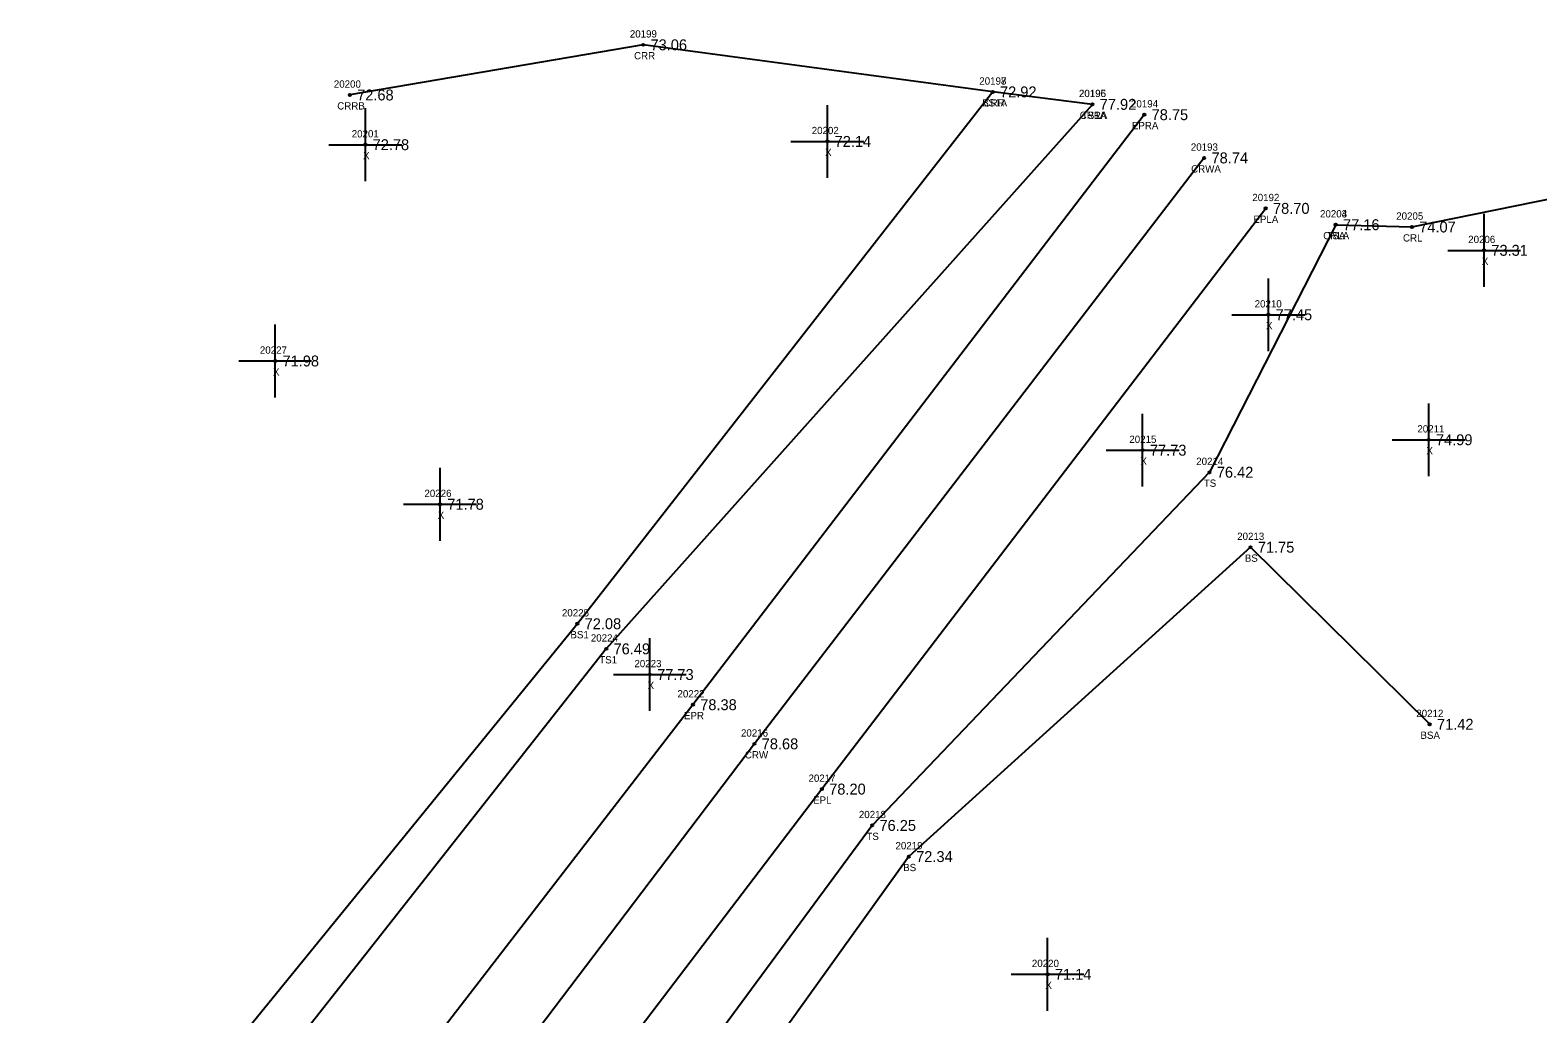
# Model space of a CAD drawing. Extents: x 2505300 to 2506184, y 912965 to 913825.
# Drawn here: x 2505870.9 to 2506078.1, y 913689.6 to 913824.7 of the extents above; entities that cross this region are included whole.
import ezdxf

# ---------------------------------------------------------------- set-up
doc = ezdxf.new("R2010")
doc.units = 0
for name, color, linetype in [('RD_DTM_BkLn1', 7, 'Continuous'), ('RD_DTM_BkLn2', 7, 'Continuous'), ('RD_DTM_BkLn_txCode', 7, 'Continuous'), ('RD_EX_H2O', 7, 'Continuous'), ('RD_EX_H2O_txCode', 7, 'Continuous'), ('RD_EX_Misc', 7, 'Continuous'), ('RD_EX_Misc_txCode', 7, 'Continuous'), ('RD_EX_Road', 7, 'Continuous'), ('RD_EX_Road_txCode', 7, 'Continuous'), ('RD_EX_TX_H2O_ELEV', 7, 'Continuous'), ('RD_EX_TX_Misc_ELEV', 7, 'Continuous'), ('RD_EX_TX_Road_ELEV', 7, 'Continuous'), ('RD_HC_Survey_ELEV', 7, 'Continuous'), ('RD_HC_Survey_txCode', 7, 'Continuous'), ('RD_SMD_Locator', 7, 'Continuous')]:
    doc.layers.add(name, color=color, linetype=linetype)

msp = doc.modelspace()

# ---------------------------------------------------------------- linework, layer by layer
at = {"layer": 'RD_DTM_BkLn1'}
msp.add_lwpolyline([(2506032.26, 913807.16), (2505970.46, 913726.68), (2505911.98, 913649.53), (2505850.51, 913569.34), (2505823.85, 913534.92)], dxfattribs=at)
at = {"layer": 'RD_DTM_BkLn2'}
for points in [[(2506003.2, 913816.23), (2505946.13, 913743.18), (2505885.35, 913668.51), (2505838.59, 913602.48), (2505816.98, 913593.69), (2505806.53, 913576.86), (2505793.9, 913560.45)], [(2506016.9, 913814.52), (2505950.1, 913739.73), (2505890.95, 913664.65), (2505842.78, 913598.78), (2505826.57, 913582.25), (2505819.44, 913586.46), (2505803.76, 913558.88), (2505804.05, 913552.09), (2505810.12, 913545.7)], [(2506050.33, 913797.99), (2506032.99, 913763.99), (2505986.64, 913715.48), (2505928.41, 913636.56), (2505869.01, 913554.3), (2505845.62, 913525.11), (2505838.24, 913524.07)], [(2506063.24, 913729.37), (2506038.62, 913753.69), (2505991.68, 913711.2), (2505934.4, 913631.37), (2505905.82, 913578.23), (2505899.85, 913572.14), (2505876.49, 913544.36), (2505856.4, 913524.92), (2505848.42, 913517.19)]]:
    msp.add_lwpolyline(points, dxfattribs=at)
at = {"layer": 'RD_EX_H2O'}
for points in [[(2506016.9, 913814.52), (2506003.2, 913816.23), (2505955.18, 913822.7), (2505914.87, 913815.81)], [(2506050.33, 913797.99), (2506060.8, 913797.68), (2506089.41, 913803.52), (2506128.64, 913810.3)]]:
    msp.add_lwpolyline(points, dxfattribs=at)
at = {"layer": 'RD_EX_Misc'}
for p, q in [((2505917, 913803.98), (2505917, 913813.98)), ((2505980.48, 913804.43), (2505980.48, 913814.43)), ((2505975.48, 913809.43), (2505985.48, 913809.43)), ((2505912, 913808.98), (2505922, 913808.98)), ((2506070.71, 913789.47), (2506070.71, 913799.47)), ((2506065.71, 913794.47), (2506075.71, 913794.47)), ((2506041.07, 913780.62), (2506041.07, 913790.62)), ((2506036.07, 913785.62), (2506046.07, 913785.62)), ((2505904.62, 913774.27), (2505904.62, 913784.27)), ((2505899.62, 913779.27), (2505909.62, 913779.27)), ((2506023.8, 913762.02), (2506023.8, 913772.02)), ((2506063.1, 913763.45), (2506063.1, 913773.45)), ((2506058.1, 913768.45), (2506068.1, 913768.45)), ((2506018.8, 913767.02), (2506028.8, 913767.02)), ((2505927.26, 913754.59), (2505927.26, 913764.59)), ((2505922.26, 913759.59), (2505932.26, 913759.59)), ((2505956.09, 913731.21), (2505956.09, 913741.21)), ((2505951.09, 913736.21), (2505961.09, 913736.21)), ((2506010.74, 913690.03), (2506010.74, 913700.03)), ((2506005.74, 913695.03), (2506015.74, 913695.03))]:
    msp.add_line(p, q, dxfattribs=at)
at = {"layer": 'RD_EX_Road'}
for points in [[(2506024.03, 913813.1), (2505962.01, 913732.06), (2505903.3, 913655.93), (2505840.88, 913574.4), (2505819.41, 913546.54), (2505814.19, 913542.64)], [(2506040.71, 913800.23), (2505979.73, 913720.47), (2505920.44, 913642.61), (2505859.42, 913562.61), (2505835.44, 913531.43), (2505833.77, 913527.25)]]:
    msp.add_lwpolyline(points, dxfattribs=at)
at = {"layer": 'RD_SMD_Locator'}
for centre in [(2505955.18, 913822.7), (2505914.87, 913815.81), (2506003.2, 913816.23), (2506003.2, 913816.23), (2506016.9, 913814.52), (2506016.9, 913814.52), (2506024.03, 913813.1), (2505980.48, 913809.43), (2505917, 913808.98), (2506032.26, 913807.16), (2506040.71, 913800.23), (2506050.33, 913797.99), (2506050.33, 913797.99), (2506060.8, 913797.68), (2506070.71, 913794.47), (2506041.07, 913785.62), (2505904.62, 913779.27), (2506063.1, 913768.45), (2506023.8, 913767.02), (2506032.99, 913763.99), (2505927.26, 913759.59), (2506038.62, 913753.69), (2505946.13, 913743.18), (2505950.1, 913739.73), (2505956.09, 913736.21), (2505962.01, 913732.06), (2506063.24, 913729.37), (2505970.46, 913726.68), (2505979.73, 913720.47), (2505986.64, 913715.48), (2505991.68, 913711.2), (2506010.74, 913695.03)]:
    msp.add_circle(centre, 0.15, dxfattribs=at)

# ---------------------------------------------------------------- texts
at = {"layer": 'RD_DTM_BkLn_txCode'}
for s, p in [('20198', (2506001.36, 913817.23)), ('20195', (2506015.06, 913815.52)), ('BS1A', (2506001.76, 913814.23)), ('TS1A', (2506015.45, 913812.52)), ('20203', (2506048.17, 913798.99)), ('TSA', (2506049.05, 913795.99)), ('20214', (2506031.16, 913764.99)), ('TS', (2506032.2, 913761.99)), ('20213', (2506036.79, 913754.69)), ('BS', (2506037.84, 913751.69)), ('20225', (2505944.01, 913744.18)), ('BS1', (2505945.18, 913741.18)), ('20224', (2505947.98, 913740.73)), ('TS1', (2505949.14, 913737.73)), ('20212', (2506061.4, 913730.37)), ('BSA', (2506061.97, 913727.37)), ('20218', (2505984.81, 913716.48)), ('TS', (2505985.84, 913713.48)), ('20219', (2505989.84, 913712.2)), ('BS', (2505990.9, 913709.2))]:
    msp.add_text(s, height=1, dxfattribs=at).set_placement(p)
at = {"layer": 'RD_EX_H2O_txCode'}
for s, p in [('20199', (2505953.34, 913823.7)), ('CRR', (2505953.92, 913820.7)), ('20200', (2505912.67, 913816.81)), ('20197', (2506001.36, 913817.23)), ('20196', (2506015.04, 913815.52)), ('CRRB', (2505913.14, 913813.81)), ('CRR', (2506001.94, 913814.23)), ('CRRA', (2506015.15, 913812.52)), ('20204', (2506048.17, 913798.99)), ('20205', (2506058.64, 913798.68)), ('CRLA', (2506048.61, 913795.99)), ('CRL', (2506059.57, 913795.68))]:
    msp.add_text(s, height=1, dxfattribs=at).set_placement(p)
at = {"layer": 'RD_EX_Misc_txCode'}
for s, p in [('20202', (2505978.33, 913810.43)), ('20201', (2505915.13, 913809.98)), ('X', (2505916.69, 913806.98)), ('X', (2505980.17, 913807.43)), ('20206', (2506068.53, 913795.47)), ('X', (2506070.4, 913792.47)), ('20210', (2506039.19, 913786.62)), ('X', (2506040.75, 913783.62)), ('20227', (2505902.51, 913780.27)), ('X', (2505904.31, 913777.27)), ('20211', (2506061.55, 913769.45)), ('20215', (2506021.97, 913768.02)), ('X', (2506023.49, 913765.02)), ('X', (2506062.79, 913766.45)), ('20226', (2505925.12, 913760.59)), ('X', (2505926.95, 913757.59)), ('20223', (2505953.97, 913737.21)), ('X', (2505955.78, 913734.21)), ('20220', (2506008.58, 913696.03)), ('X', (2506010.43, 913693.03))]:
    msp.add_text(s, height=1, dxfattribs=at).set_placement(p)
at = {"layer": 'RD_EX_Road_txCode'}
for s, p in [('20194', (2506022.2, 913814.1)), ('EPRA', (2506022.32, 913811.1)), ('20192', (2506038.87, 913801.23)), ('EPLA', (2506039.02, 913798.23)), ('20222', (2505959.89, 913733.06)), ('EPR', (2505960.78, 913730.06)), ('20217', (2505977.89, 913721.47)), ('EPL', (2505978.52, 913718.47))]:
    msp.add_text(s, height=1, dxfattribs=at).set_placement(p)
at = {"layer": 'RD_EX_TX_H2O_ELEV'}
for s, p in [('73.06', (2505956.18, 913821.95)), ('72.68', (2505915.87, 913815.06)), ('72.92', (2506004.2, 913815.48)), ('77.92', (2506017.9, 913813.77)), ('77.16', (2506051.33, 913797.24)), ('74.07', (2506061.8, 913796.93))]:
    msp.add_text(s, height=1.5, dxfattribs=at).set_placement(p)
at = {"layer": 'RD_EX_TX_Misc_ELEV'}
for s, p in [('72.92', (2506004.2, 913815.48)), ('77.92', (2506017.9, 913813.77)), ('72.78', (2505918, 913808.23)), ('72.14', (2505981.48, 913808.68)), ('77.16', (2506051.33, 913797.24)), ('73.31', (2506071.71, 913793.72)), ('77.45', (2506042.07, 913784.87)), ('71.98', (2505905.62, 913778.52)), ('77.73', (2506024.8, 913766.27)), ('74.99', (2506064.1, 913767.7)), ('76.42', (2506033.99, 913763.24)), ('71.78', (2505928.26, 913758.84)), ('71.75', (2506039.62, 913752.94)), ('72.08', (2505947.13, 913742.43)), ('76.49', (2505951.1, 913738.98)), ('77.73', (2505957.09, 913735.46)), ('71.42', (2506064.24, 913728.62)), ('76.25', (2505987.64, 913714.73)), ('72.34', (2505992.68, 913710.45)), ('71.14', (2506011.74, 913694.28))]:
    msp.add_text(s, height=1.5, dxfattribs=at).set_placement(p)
at = {"layer": 'RD_EX_TX_Road_ELEV'}
for s, p in [('78.75', (2506025.03, 913812.35)), ('78.70', (2506041.71, 913799.48)), ('78.38', (2505963.01, 913731.31)), ('78.20', (2505980.73, 913719.72))]:
    msp.add_text(s, height=1.5, dxfattribs=at).set_placement(p)
at = {"layer": 'RD_HC_Survey_ELEV'}
for s, p in [('78.74', (2506033.26, 913806.41)), ('78.68', (2505971.46, 913725.93))]:
    msp.add_text(s, height=1.5, dxfattribs=at).set_placement(p)
at = {"layer": 'RD_HC_Survey_txCode'}
for s, p in [('20193', (2506030.42, 913808.16)), ('CRWA', (2506030.46, 913805.16)), ('20216', (2505968.61, 913727.68)), ('CRW', (2505969.15, 913724.68))]:
    msp.add_text(s, height=1, dxfattribs=at).set_placement(p)

doc.saveas('drawing.dxf')
